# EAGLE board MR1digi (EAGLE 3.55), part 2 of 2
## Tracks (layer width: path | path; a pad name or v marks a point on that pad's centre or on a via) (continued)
N$578  (via drill 0.61 pad 1.78) (continued)
  other vias: 94.45,115.88
N$579  (via drill 0.61 pad 1.78)
  other vias: 94.45,113.34
N$580  (via drill 0.61 pad 1.78)
  other vias: 94.45,110.8
N$581  (via drill 0.61 pad 1.78)
  other vias: 94.45,108.26
N$582  (via drill 0.61 pad 1.78)
  other vias: 94.45,105.72
N$583  (via drill 0.61 pad 1.78)
  other vias: 96.99,105.72
N$584  (via drill 0.61 pad 1.78)
  other vias: 96.99,108.26
N$585  (via drill 0.61 pad 1.78)
  other vias: 96.99,110.8
N$586  (via drill 0.61 pad 1.78)
  other vias: 96.99,113.34
N$587  (via drill 0.61 pad 1.78)
  other vias: 96.99,115.88
N$588  (via drill 0.61 pad 1.78)
  other vias: 96.99,118.42
N$589  (via drill 0.61 pad 1.78)
  other vias: 96.99,120.96
N$590  (via drill 0.61 pad 1.78)
  other vias: 96.99,123.5
N$591  (via drill 0.61 pad 1.78)
  other vias: 96.99,126.04
N$592  (via drill 0.61 pad 1.78)
  other vias: 96.99,128.58
N$593  (via drill 0.61 pad 1.78)
  other vias: 53.81,143.82
N$594  (via drill 0.61 pad 1.78)
  other vias: 84.29,151.44
N$595  (via drill 0.61 pad 1.78)
  other vias: 84.29,148.9
N$596  (via drill 0.61 pad 1.78)
  other vias: 84.29,146.36
N$597  (via drill 0.61 pad 1.78)
  other vias: 84.29,143.82
N$598  (via drill 0.61 pad 1.78)
  other vias: 84.29,141.28
N$599  (via drill 0.61 pad 1.78)
  other vias: 84.29,138.74
N$600  (via drill 0.61 pad 1.78)
  other vias: 84.29,136.2
N$601  (via drill 0.61 pad 1.78)
  other vias: 84.29,133.66
N$602  (via drill 0.61 pad 1.78)
  other vias: 84.29,131.12
N$603  (via drill 0.61 pad 1.78)
  other vias: 86.83,131.12
N$604  (via drill 0.61 pad 1.78)
  other vias: 86.83,133.66
N$605  (via drill 0.61 pad 1.78)
  other vias: 86.83,136.2
N$606  (via drill 0.61 pad 1.78)
  other vias: 86.83,138.74
N$607  (via drill 0.61 pad 1.78)
  other vias: 86.83,141.28
N$608  (via drill 0.61 pad 1.78)
  other vias: 86.83,143.82
N$609  (via drill 0.61 pad 1.78)
  other vias: 86.83,146.36
N$610  (via drill 0.61 pad 1.78)
  other vias: 86.83,148.9
N$611  (via drill 0.61 pad 1.78)
  other vias: 86.83,151.44
N$612  (via drill 0.61 pad 1.78)
  other vias: 53.81,141.28
N$613  (via drill 0.61 pad 1.78)
  other vias: 89.37,151.44
N$614  (via drill 0.61 pad 1.78)
  other vias: 89.37,148.9
N$615  (via drill 0.61 pad 1.78)
  other vias: 89.37,146.36
N$616  (via drill 0.61 pad 1.78)
  other vias: 53.81,138.74
N$617  (via drill 0.61 pad 1.78)
  other vias: 89.37,143.82
N$618  (via drill 0.61 pad 1.78)
  other vias: 89.37,141.28
N$619  (via drill 0.61 pad 1.78)
  other vias: 89.37,138.74
N$620  (via drill 0.61 pad 1.78)
  other vias: 89.37,136.2
N$621  (via drill 0.61 pad 1.78)
  other vias: 89.37,133.66
N$622  (via drill 0.61 pad 1.78)
  other vias: 89.37,131.12
N$623  (via drill 0.61 pad 1.78)
  other vias: 91.91,131.12
N$624  (via drill 0.61 pad 1.78)
  other vias: 91.91,133.66
N$625  (via drill 0.61 pad 1.78)
  other vias: 91.91,136.2
N$626  (via drill 0.61 pad 1.78)
  other vias: 91.91,138.74
N$627  (via drill 0.61 pad 1.78)
  other vias: 91.91,141.28
N$628  (via drill 0.61 pad 1.78)
  other vias: 91.91,143.82
N$629  (via drill 0.61 pad 1.78)
  other vias: 91.91,146.36
N$630  (via drill 0.61 pad 1.78)
  other vias: 91.91,148.9
N$631  (via drill 0.61 pad 1.78)
  other vias: 91.91,151.44
N$632  (via drill 0.61 pad 1.78)
  other vias: 53.81,146.36
N$633  (via drill 0.61 pad 1.78)
  other vias: 56.35,138.74
N$634  (via drill 0.61 pad 1.78)
  other vias: 94.45,151.44
N$635  (via drill 0.61 pad 1.78)
  other vias: 94.45,148.9
N$636  (via drill 0.61 pad 1.78)
  other vias: 94.45,146.36
N$637  (via drill 0.61 pad 1.78)
  other vias: 94.45,143.82
N$638  (via drill 0.61 pad 1.78)
  other vias: 94.45,141.28
N$639  (via drill 0.61 pad 1.78)
  other vias: 94.45,138.74
N$640  (via drill 0.61 pad 1.78)
  other vias: 94.45,136.2
N$641  (via drill 0.61 pad 1.78)
  other vias: 94.45,133.66
N$642  (via drill 0.61 pad 1.78)
  other vias: 94.45,131.12
N$643  (via drill 0.61 pad 1.78)
  other vias: 96.99,131.12
N$644  (via drill 0.61 pad 1.78)
  other vias: 96.99,133.66
N$645  (via drill 0.61 pad 1.78)
  other vias: 96.99,136.2
N$646  (via drill 0.61 pad 1.78)
  other vias: 96.99,138.74
N$647  (via drill 0.61 pad 1.78)
  other vias: 96.99,141.28
N$648  (via drill 0.61 pad 1.78)
  other vias: 96.99,143.82
N$649  (via drill 0.61 pad 1.78)
  other vias: 96.99,146.36
N$650  (via drill 0.61 pad 1.78)
  other vias: 96.99,148.9
N$651  (via drill 0.61 pad 1.78)
  other vias: 96.99,151.44
N$652  (via drill 0.61 pad 1.78)
  other vias: 56.35,141.28
N$653  (via drill 0.61 pad 1.78)
  other vias: 56.35,143.82
N$654  (via drill 0.61 pad 1.78)
  other vias: 56.35,146.36
N$655  (via drill 0.61 pad 1.78)
  other vias: 58.89,146.36
N$656  (via drill 0.61 pad 1.78)
  other vias: 58.89,143.82
N$657  (via drill 0.61 pad 1.78)
  other vias: 58.89,141.28
N$658  (via drill 0.61 pad 1.78)
  other vias: 58.89,138.74
N$659  (via drill 0.61 pad 1.78)
  other vias: 61.43,138.74
N$660  (via drill 0.61 pad 1.78)
  other vias: 61.43,141.28
N$661  (via drill 0.61 pad 1.78)
  other vias: 61.43,143.82
N$662  (via drill 0.61 pad 1.78)
  other vias: 61.43,146.36
N$663  (via drill 0.61 pad 1.78)
  other vias: 63.97,143.82
N$664  (via drill 0.61 pad 1.78)
  other vias: 63.97,141.28
N$665  (via drill 0.61 pad 1.78)
  other vias: 63.97,138.74
N$666  (via drill 0.61 pad 1.78)
  other vias: 63.97,146.36
N$667  (via drill 0.61 pad 1.78)
  other vias: 66.51,138.74
N$668  (via drill 0.61 pad 1.78)
  other vias: 66.51,141.28
N$669  (via drill 0.61 pad 1.78)
  other vias: 66.51,143.82
N$670  (via drill 0.61 pad 1.78)
  other vias: 66.51,146.36
N$671  (via drill 0.61 pad 1.78)
  other vias: 69.05,146.36
N$672  (via drill 0.61 pad 1.78)
  other vias: 69.05,143.82
N$673  (via drill 0.61 pad 1.78)
  other vias: 69.05,141.28
N$674  (via drill 0.61 pad 1.78)
  other vias: 69.05,138.74
N$675  (via drill 0.61 pad 1.78)
  other vias: 71.59,138.74
N$676  (via drill 0.61 pad 1.78)
  other vias: 71.59,141.28
N$677  (via drill 0.61 pad 1.78)
  other vias: 71.59,143.82
N$678  (via drill 0.61 pad 1.78)
  other vias: 71.59,146.36
N$679  (via drill 0.61 pad 1.78)
  other vias: 74.13,143.82
N$680  (via drill 0.61 pad 1.78)
  other vias: 74.13,141.28
N$681  (via drill 0.61 pad 1.78)
  other vias: 74.13,138.74
N$682  (via drill 0.61 pad 1.78)
  other vias: 74.13,146.36
N$683  (via drill 0.61 pad 1.78)
  other vias: 76.67,138.74
N$684  (via drill 0.61 pad 1.78)
  other vias: 76.67,141.28
N$685  (via drill 0.61 pad 1.78)
  other vias: 76.67,143.82
N$686  (via drill 0.61 pad 1.78)
  other vias: 76.67,146.36
N$687  (via drill 0.61 pad 1.78)
  other vias: 79.21,146.36
N$688  (via drill 0.61 pad 1.78)
  other vias: 79.21,143.82
N$689  (via drill 0.61 pad 1.78)
  other vias: 79.21,141.28
N$690  (via drill 0.61 pad 1.78)
  other vias: 79.21,138.74
N$691  (via drill 0.61 pad 1.78)
  other vias: 81.75,138.74
N$692  (via drill 0.61 pad 1.78)
  other vias: 81.75,141.28
N$693  (via drill 0.61 pad 1.78)
  other vias: 81.75,143.82
N$694  (via drill 0.61 pad 1.78)
  other vias: 81.75,146.36
N$695  (via drill 0.61 pad 1.78)
  other vias: 53.81,148.9
N$696  (via drill 0.61 pad 1.78)
  other vias: 53.81,151.44
N$697  (via drill 0.61 pad 1.78)
  other vias: 56.35,148.9
N$698  (via drill 0.61 pad 1.78)
  other vias: 56.35,151.44
N$699  (via drill 0.61 pad 1.78)
  other vias: 58.89,151.44
N$700  (via drill 0.61 pad 1.78)
  other vias: 58.89,148.9
N$701  (via drill 0.61 pad 1.78)
  other vias: 61.43,148.9
N$702  (via drill 0.61 pad 1.78)
  other vias: 61.43,151.44
N$703  (via drill 0.61 pad 1.78)
  other vias: 63.97,148.9
N$704  (via drill 0.61 pad 1.78)
  other vias: 63.97,151.44
N$705  (via drill 0.61 pad 1.78)
  other vias: 66.51,148.9
N$706  (via drill 0.61 pad 1.78)
  other vias: 66.51,151.44
N$707  (via drill 0.61 pad 1.78)
  other vias: 69.05,151.44
N$708  (via drill 0.61 pad 1.78)
  other vias: 69.05,148.9
N$709  (via drill 0.61 pad 1.78)
  other vias: 71.59,148.9
N$710  (via drill 0.61 pad 1.78)
  other vias: 71.59,151.44
N$711  (via drill 0.61 pad 1.78)
  other vias: 74.13,148.9
N$712  (via drill 0.61 pad 1.78)
  other vias: 74.13,151.44
N$713  (via drill 0.61 pad 1.78)
  other vias: 76.67,148.9
N$714  (via drill 0.61 pad 1.78)
  other vias: 76.67,151.44
N$715  (via drill 0.61 pad 1.78)
  other vias: 79.21,151.44
N$716  (via drill 0.61 pad 1.78)
  other vias: 79.21,148.9
N$717  (via drill 0.61 pad 1.78)
  other vias: 81.75,148.9
N$718  (via drill 0.61 pad 1.78)
  other vias: 81.75,151.44
N$719
  Bottom 0.406: R12. 15.71,57.46 15.71,59.88 TH1. | R5. 15.71,54.92 15.71,57.34 R12. | C22. 18.25,57.46 R12.
N$720
  Top 0.406: R3. 58.59,54.29 53.81,54.29 48.09,48.57 48.09,44.76 38.57,44.76
N$721
  Top 0.406: 59.22,56.83 57.95,55.56 53.81,55.56 47.46,49.21 44.28,49.21 41.11,46.03 37.94,46.03 37.3,45.4 37.3,44.13 36.66,43.49 36.03,43.49
N$722
  Bottom 0.406: R13. 11.27,34.6 | 8.09,42.22 9.36,40.95 9.36,34.6 11.27,34.6 | 11.27,35.25 11.27,35.24 11.27,34.6
N$732  (via drill 0.61 pad 1.78)
  other vias: 48.73,87.94
N$733  (via drill 0.61 pad 1.78)
  other vias: 48.73,90.48
N$734  (via drill 0.61 pad 1.78)
  other vias: 48.73,93.02
N$735  (via drill 0.61 pad 1.78)
  other vias: 48.73,95.56
N$736  (via drill 0.61 pad 1.78)
  other vias: 48.73,98.1
N$737  (via drill 0.61 pad 1.78)
  other vias: 48.73,100.64
N$738  (via drill 0.61 pad 1.78)
  other vias: 48.73,103.18
N$739  (via drill 0.61 pad 1.78)
  other vias: 48.73,105.72
N$740  (via drill 0.61 pad 1.78)
  other vias: 48.73,108.26
N$741  (via drill 0.61 pad 1.78)
  other vias: 48.73,110.8
N$742  (via drill 0.61 pad 1.78)
  other vias: 51.27,110.8
N$743  (via drill 0.61 pad 1.78)
  other vias: 51.27,108.26
N$744  (via drill 0.61 pad 1.78)
  other vias: 51.27,105.72
N$745  (via drill 0.61 pad 1.78)
  other vias: 51.27,103.18
N$746  (via drill 0.61 pad 1.78)
  other vias: 51.27,100.64
N$747  (via drill 0.61 pad 1.78)
  other vias: 51.27,98.1
N$748  (via drill 0.61 pad 1.78)
  other vias: 51.27,95.56
N$749  (via drill 0.61 pad 1.78)
  other vias: 51.27,93.02
N$750  (via drill 0.61 pad 1.78)
  other vias: 51.27,90.48
N$751  (via drill 0.61 pad 1.78)
  other vias: 51.27,87.94
N$762  (via drill 0.61 pad 1.78)
  other vias: 48.73,113.34
N$763  (via drill 0.61 pad 1.78)
  other vias: 48.73,115.88
N$764  (via drill 0.61 pad 1.78)
  other vias: 48.73,118.42
N$765  (via drill 0.61 pad 1.78)
  other vias: 48.73,120.96
N$766  (via drill 0.61 pad 1.78)
  other vias: 48.73,123.5
N$767  (via drill 0.61 pad 1.78)
  other vias: 48.73,126.04
N$768  (via drill 0.61 pad 1.78)
  other vias: 48.73,128.58
N$769  (via drill 0.61 pad 1.78)
  other vias: 48.73,131.12
N$770  (via drill 0.61 pad 1.78)
  other vias: 48.73,133.66
N$771  (via drill 0.61 pad 1.78)
  other vias: 48.73,136.2
N$772  (via drill 0.61 pad 1.78)
  other vias: 51.27,136.2
N$773  (via drill 0.61 pad 1.78)
  other vias: 51.27,133.66
N$774  (via drill 0.61 pad 1.78)
  other vias: 51.27,131.12
N$775  (via drill 0.61 pad 1.78)
  other vias: 51.27,128.58
N$776  (via drill 0.61 pad 1.78)
  other vias: 51.27,126.04
N$777  (via drill 0.61 pad 1.78)
  other vias: 51.27,123.5
N$778  (via drill 0.61 pad 1.78)
  other vias: 51.27,120.96
N$779  (via drill 0.61 pad 1.78)
  other vias: 51.27,118.42
N$780  (via drill 0.61 pad 1.78)
  other vias: 51.27,115.88
N$781  (via drill 0.61 pad 1.78)
  other vias: 51.27,113.34
N$786  (via drill 0.61 pad 1.78)
  other vias: 48.73,138.74
N$787  (via drill 0.61 pad 1.78)
  other vias: 48.73,141.28
N$788  (via drill 0.61 pad 1.78)
  other vias: 48.73,143.82
N$789  (via drill 0.61 pad 1.78)
  other vias: 48.73,146.36
N$790  (via drill 0.61 pad 1.78)
  other vias: 51.27,146.36
N$791  (via drill 0.61 pad 1.78)
  other vias: 51.27,143.82
N$792  (via drill 0.61 pad 1.78)
  other vias: 51.27,141.28
N$793  (via drill 0.61 pad 1.78)
  other vias: 51.27,138.74
N$796  (via drill 0.61 pad 1.78)
  other vias: 48.73,148.9
N$797  (via drill 0.61 pad 1.78)
  other vias: 48.73,151.44
N$798  (via drill 0.61 pad 1.78)
  other vias: 51.27,151.44
N$799  (via drill 0.61 pad 1.78)
  other vias: 51.27,148.9
N$800  (via drill 0.61 pad 1.78)
  other vias: 84.29,85.4
N$801  (via drill 0.61 pad 1.78)
  other vias: 86.83,85.4
VDD  (via drill 0.61 pad 1.02, 0.61 pad 1.68)
  Top 0.406: 62.06,35.87 60.16,35.87 | C20. 70.32,35.87 69.69,35.87 | 69.37,35.87 68.41,35.87 | 60.16,35.87 60.16,34.07 58.89,34.07 58.89,33.97 57.62,33.97 57.62,34.07 | 51.91,34.07 51.91,33.97 53.81,33.97 | 56.98,35.87 60.16,35.87 | 68.41,35.87 68.41,34.07 | 68.41,35.87 62.06,35.87 | 62.06,35.24 62.06,35.87 | 62.06,35.24 C16. | 68.41,34.07 67.14,34.07 | 68.41,34.07 68.41,33.97 | 51.91,34.07 50.63,34.07 50.63,33.97 49.37,33.97 49.37,34.07 DAC1. 53.91,34.07 54.13,34.29 | 60.16,49.84 60.16,46.78 60.16,46.67 | 70.95,34.29 69.69,34.29 69.69,35.87 | 66.32,46.35 C14. 60.16,49.97 60.16,49.84 | 70.95,34.29 70.64,34.29 70.32,34.6 70.32,35.24 69.69,35.87 | 69.69,35.87 69.37,35.87 | 69.37,35.87 62.7,35.87 62.06,35.24 | 25.23,24.76 25.11,24.63 C8. 23.65,21.71 23.65,21.58 | 39.84,27.62 C9. | 39.74,25.71 39.74,27.52 39.84,27.62 | 39.74,25.71 39.84,25.71 39.84,27.62 | 74.77,34.29 74.45,34.29 | 51.91,34.07 53.71,34.07 53.81,33.97 | 55.71,35.87 56.98,35.87 | 53.81,33.97 C15. | 69.37,35.87 56.98,35.87 | 25.87,46.03 25.87,58.73 22.06,62.54 22.06,66.04 9.04,79.05 9.04,85.72 11.9,85.72 v13.17,84.45 | 51.59,2.85 34.12,2.85 29.68,7.3 29.68,7.62 29.68,10.47 | 51.59,8.57 51.59,8.89 | 54.13,34.29 53.81,33.97 | 55.71,35.87 54.13,34.29 | 55.71,35.87 70.64,35.87 70.95,35.56 70.95,34.29 | 70.95,34.29 70.95,25.08 70.64,24.76 | 23.65,21.58 25.23,23.17 25.23,24.76 | 39.74,25.71 38.57,25.71 36.03,28.25 28.73,28.25 25.23,24.76 | 25.23,24.76 25.23,22.86 24.92,22.86 23.65,21.58 | v23.65,20.63 23.65,21.58 | SV1. 45.87,53.65 40.79,48.57 37.94,48.57 37.3,47.94 37.3,47.62 36.03,46.35 36.03,46.03 | 25.87,46.03 v31.9,46.03 | 25.87,34.6 25.87,46.03 | 29.68,10.47 30.95,11.74
  Top 0.406: 29.68,6.98 29.68,10.47 | 59.84,24.76 70.95,24.76 | 70.95,34.29 74.77,34.29 | 74.77,34.29 74.77,41.59 70,46.35 66.32,46.35 | 66.32,46.35 66.19,46.35 62.7,49.84 60.16,49.84
  Top 0.61: 51.59,8.57 51.91,8.25 56.35,8.25 56.03,8.57 51.59,8.57 | 51.59,8.57 51.59,2.85 33.81,2.85 | 70.95,34.29 70.95,24.76 70.64,24.76 59.84,24.76 v56.35,21.27 | 33.81,2.85 v58.25,2.85 | 33.81,2.85 29.68,6.98 29.68,7.62
  Top 1.27: C3. 51.59,4.88 51.59,8.57 | 51.59,8.57 C4. | 51.59,8.57 55.4,8.57
  Bottom 0.406: 3.34,54.92 3.33,54.92 3.33,53.02 | D1. 3.33,52.83 3.33,53.02 | 13.17,84.13 13.17,81.28 C17. 13.17,81.4 13.17,84.13 | 13.17,84.51 v13.17,84.45 13.17,84.13 | 36.03,46.03 33.62,46.03 C12. 33.49,46.03 | C11. 24.6,42.22 25.87,42.22 | 31.91,40.32 31.91,42.22 31.91,44.46 33.49,46.03 | C11. 24.6,42.54 25.87,42.54 25.87,42.22 | C10. 13.93,47.3 8.09,47.3 5.55,47.3 3.33,49.53 3.33,53.02 | C10. 15.39,48.89 | C11. 18.06,48.89 C10. | 36.03,46.03 33.49,46.03 | 36.03,46.03 v31.9,46.03 36.03,46.03 | 22.06,33.97 22.06,35.56 | 20.79,36.51 20.79,38.09 | 25.87,42.22 25.87,34.6 | 20.79,36.51 20.79,39.05 | 20.79,36.51 21.42,35.87 21.74,35.87 22.06,35.56 | 22.06,22.22 22.06,35.56 | v23.65,20.63 30.95,13.33 30.95,11.74 | 13.17,84.13 v13.17,148.9 | C13. 22.38,68.26 22.06,67.94 22.06,62.54 22.06,68.13 C13.
  Bottom 0.61: v56.35,21.27 58.25,19.36 v58.25,2.85 | v23.65,20.63 22.06,22.22 22.06,33.97 | 20.79,38.09 20.79,39.05 23.96,42.22 25.87,42.22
